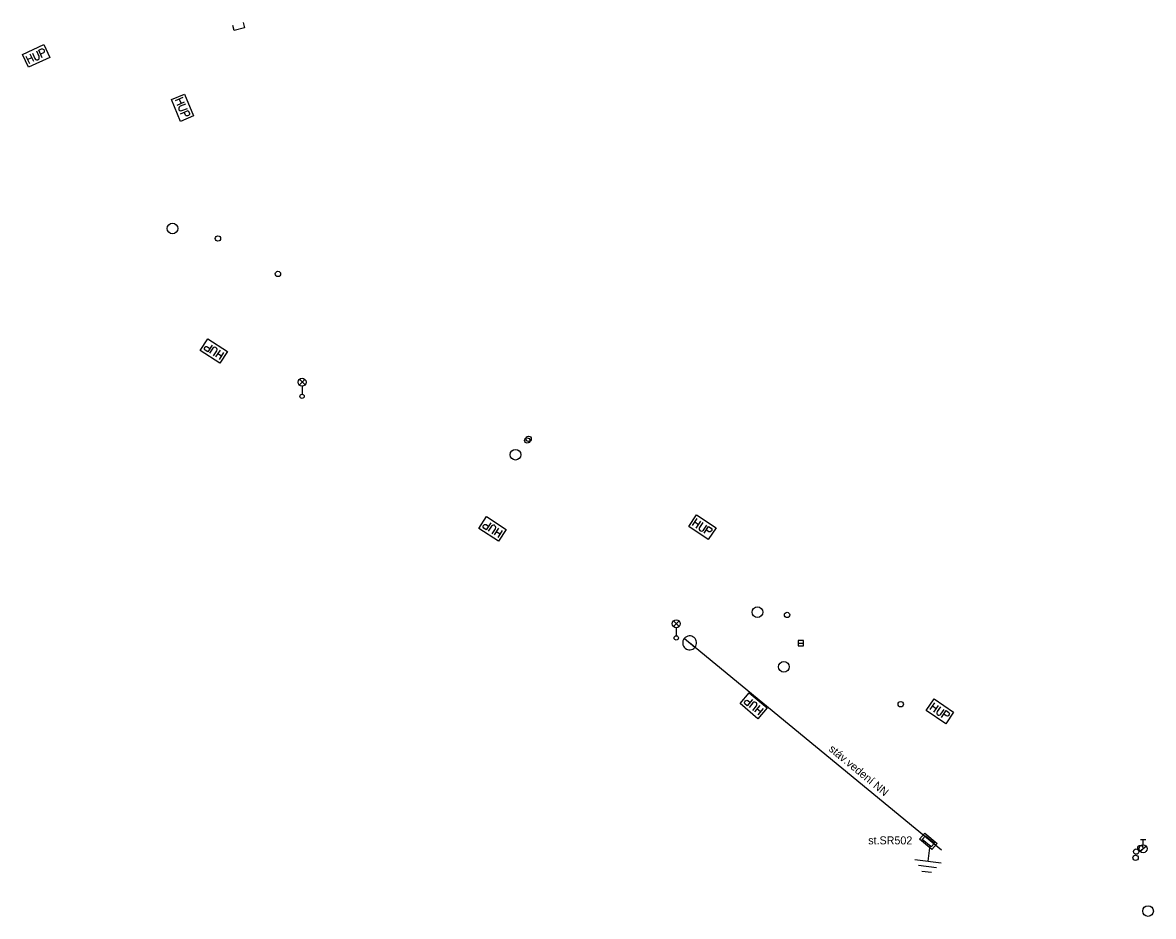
# Model space of a CAD drawing. Extents: x -762500 to -761250, y -1152983 to -1152297.
# Drawn here: x -761356.3 to -761250.4, y -1152619.7 to -1152536 of the extents above; entities that cross this region are included whole.
import ezdxf

# ---------------------------------------------------------------- set-up
doc = ezdxf.new("R2010")
doc.units = 0
for name, color, linetype in [('Vrstva 1', 7, 'Continuous'), ('Vrstva 2', 7, 'Continuous'), ('Vrstva 9', 7, 'Continuous')]:
    doc.layers.add(name, color=color, linetype=linetype)

msp = doc.modelspace()

# ---------------------------------------------------------------- linework, layer by layer
at = {"layer": 'Vrstva 1'}
for p, q in [((-761293.372, -1152594.478), (-761294.368, -1152593.642)), ((-761270.28, -1152613.45), (-761293.87, -1152594.06)), ((-761271.539, -1152614.483), (-761271.351, -1152612.995)), ((-761272.779, -1152614.327), (-761270.298, -1152614.639)), ((-761272.444, -1152614.873), (-761270.758, -1152615.085)), ((-761272.11, -1152615.419), (-761271.217, -1152615.532))]:
    msp.add_line(p, q, dxfattribs=at)
msp.add_lwpolyline([(-761335.695, -1152535.995), (-761335.561, -1152536.477), (-761336.525, -1152536.745), (-761336.659, -1152536.263)], dxfattribs=at)
for points in [[(-761271.173, -1152613.406), (-761272.326, -1152612.447), (-761271.847, -1152611.87), (-761270.693, -1152612.83)], [(-761271.231, -1152613.163), (-761272.077, -1152612.46), (-761271.789, -1152612.114), (-761270.943, -1152612.817)]]:
    msp.add_lwpolyline(points, close=True, dxfattribs=at)
for start, end in [(140.00887, 320.00887), (320.00887, 140.00887)]:
    msp.add_arc((-761293.87, -1152594.06), 0.65, start, end, dxfattribs=at)
at = {"layer": 'Vrstva 9'}
for p, q in [((-761330.434, -1152569.918), (-761329.906, -1152569.39)), ((-761329.898, -1152569.915), (-761330.426, -1152569.386)), ((-761330.17, -1152570.03), (-761330.17, -1152570.78)), ((-761295.384, -1152592.528), (-761294.856, -1152592)), ((-761294.848, -1152592.525), (-761295.376, -1152591.996)), ((-761295.12, -1152592.64), (-761295.12, -1152593.39)), ((-761283.71, -1152594.09), (-761283.21, -1152594.09)), ((-761251.64, -1152612.455), (-761251.14, -1152612.455)), ((-761251.39, -1152612.955), (-761251.39, -1152612.455)), ((-761251.684, -1152613.561), (-761251.094, -1152613.098))]:
    msp.add_line(p, q, dxfattribs=at)
for points in [[(-761356.35, -1152538.968), (-761354.35, -1152538.052), (-761353.8, -1152539.252), (-761355.8, -1152540.168), (-761356.35, -1152538.968)], [(-761355.435, -1152538.852), (-761355.205, -1152539.353), (-761355.132, -1152539.439), (-761355.04, -1152539.477), (-761354.94, -1152539.472), (-761354.883, -1152539.445), (-761354.814, -1152539.373), (-761354.787, -1152539.28), (-761354.803, -1152539.169), (-761355.033, -1152538.667)], [(-761354.835, -1152538.577), (-761354.575, -1152538.458), (-761354.476, -1152538.453), (-761354.431, -1152538.472), (-761354.373, -1152538.524), (-761354.327, -1152538.624), (-761354.325, -1152538.704), (-761354.34, -1152538.749), (-761354.409, -1152538.821), (-761354.669, -1152538.94)], [(-761354.514, -1152539.277), (-761354.835, -1152538.577)], [(-761356.035, -1152539.126), (-761355.715, -1152539.826)], [(-761355.884, -1152539.456), (-761355.482, -1152539.272)], [(-761355.313, -1152539.642), (-761355.633, -1152538.942)], [(-761341.172, -1152542.698), (-761340.329, -1152544.73), (-761341.548, -1152545.236), (-761342.392, -1152543.204), (-761341.172, -1152542.698)], [(-761341.342, -1152543.007), (-761342.053, -1152543.302)], [(-761341.884, -1152543.71), (-761341.173, -1152543.415)], [(-761341.089, -1152543.616), (-761341.599, -1152543.828), (-761341.687, -1152543.898), (-761341.728, -1152543.989), (-761341.727, -1152544.089), (-761341.703, -1152544.147), (-761341.633, -1152544.219), (-761341.541, -1152544.249), (-761341.43, -1152544.236), (-761340.92, -1152544.024)], [(-761341.677, -1152543.146), (-761341.508, -1152543.554)], [(-761341.547, -1152544.521), (-761340.836, -1152544.226)], [(-761340.836, -1152544.226), (-761340.727, -1152544.49), (-761340.725, -1152544.589), (-761340.746, -1152544.633), (-761340.801, -1152544.69), (-761340.902, -1152544.732), (-761340.982, -1152544.731), (-761341.027, -1152544.714), (-761341.096, -1152544.643), (-761341.206, -1152544.379)], [(-761337.864, -1152567.885), (-761339.718, -1152566.7), (-761339.007, -1152565.588), (-761337.153, -1152566.772), (-761337.864, -1152567.885)], [(-761339.014, -1152566.823), (-761339.255, -1152566.669), (-761339.312, -1152566.589), (-761339.321, -1152566.541), (-761339.308, -1152566.463), (-761339.249, -1152566.371), (-761339.183, -1152566.326), (-761339.137, -1152566.314), (-761339.039, -1152566.332), (-761338.798, -1152566.486)], [(-761338.599, -1152566.175), (-761339.014, -1152566.823)], [(-761338.457, -1152567.179), (-761338.16, -1152566.714), (-761338.128, -1152566.606), (-761338.146, -1152566.508), (-761338.205, -1152566.427), (-761338.258, -1152566.393), (-761338.356, -1152566.374), (-761338.448, -1152566.402), (-761338.533, -1152566.476), (-761338.83, -1152566.941)], [(-761337.859, -1152566.648), (-761338.274, -1152567.296)], [(-761337.706, -1152567.229), (-761338.078, -1152566.991)], [(-761337.901, -1152567.534), (-761337.487, -1152566.886)], [(-761311.776, -1152584.546), (-761313.621, -1152583.348), (-761312.903, -1152582.241), (-761311.057, -1152583.439), (-761311.776, -1152584.546)], [(-761293.218, -1152582.071), (-761291.391, -1152583.296), (-761292.126, -1152584.393), (-761293.954, -1152583.167), (-761293.218, -1152582.071)], [(-761312.918, -1152583.477), (-761313.158, -1152583.321), (-761313.215, -1152583.24), (-761313.223, -1152583.192), (-761313.21, -1152583.115), (-761313.15, -1152583.023), (-761313.084, -1152582.978), (-761313.037, -1152582.967), (-761312.94, -1152582.986), (-761312.7, -1152583.142)], [(-761312.499, -1152582.831), (-761312.918, -1152583.477)], [(-761312.364, -1152583.836), (-761312.064, -1152583.373), (-761312.031, -1152583.266), (-761312.048, -1152583.168), (-761312.106, -1152583.086), (-761312.159, -1152583.052), (-761312.257, -1152583.032), (-761312.35, -1152583.059), (-761312.435, -1152583.133), (-761312.735, -1152583.596)], [(-761293.189, -1152582.422), (-761293.618, -1152583.061)], [(-761293.391, -1152582.723), (-761293.024, -1152582.97)], [(-761293.251, -1152583.308), (-761292.822, -1152582.668)], [(-761292.641, -1152582.79), (-761292.948, -1152583.248), (-761292.983, -1152583.355), (-761292.967, -1152583.453), (-761292.91, -1152583.536), (-761292.858, -1152583.571), (-761292.76, -1152583.592), (-761292.667, -1152583.567), (-761292.581, -1152583.494), (-761292.274, -1152583.036)], [(-761292.521, -1152583.797), (-761292.093, -1152583.157)], [(-761292.093, -1152583.157), (-761291.855, -1152583.316), (-761291.799, -1152583.398), (-761291.792, -1152583.447), (-761291.806, -1152583.524), (-761291.867, -1152583.615), (-761291.934, -1152583.658), (-761291.981, -1152583.669), (-761292.078, -1152583.649), (-761292.315, -1152583.489)], [(-761311.762, -1152583.309), (-761312.181, -1152583.955)], [(-761311.613, -1152583.891), (-761311.984, -1152583.651)], [(-761311.811, -1152584.196), (-761311.392, -1152583.55)], [(-761287.466, -1152601.158), (-761289.151, -1152599.744), (-761288.302, -1152598.733), (-761286.618, -1152600.147), (-761287.466, -1152601.158)], [(-761288.469, -1152599.957), (-761288.688, -1152599.774), (-761288.735, -1152599.686), (-761288.737, -1152599.637), (-761288.714, -1152599.562), (-761288.643, -1152599.478), (-761288.573, -1152599.442), (-761288.525, -1152599.436), (-761288.431, -1152599.467), (-761288.212, -1152599.651)], [(-761287.974, -1152599.368), (-761288.469, -1152599.957)], [(-761287.963, -1152600.382), (-761287.608, -1152599.959), (-761287.563, -1152599.856), (-761287.568, -1152599.757), (-761287.615, -1152599.669), (-761287.664, -1152599.628), (-761287.759, -1152599.597), (-761287.854, -1152599.612), (-761287.947, -1152599.675), (-761288.302, -1152600.098)], [(-761287.301, -1152599.932), (-761287.796, -1152600.522)], [(-761287.225, -1152600.528), (-761287.563, -1152600.244)], [(-761287.458, -1152600.806), (-761286.963, -1152600.216)], [(-761270.959, -1152599.31), (-761269.138, -1152600.546), (-761269.88, -1152601.638), (-761271.7, -1152600.402), (-761270.959, -1152599.31)], [(-761270.931, -1152599.661), (-761271.364, -1152600.298)], [(-761271.135, -1152599.961), (-761270.769, -1152600.21)], [(-761270.998, -1152600.546), (-761270.565, -1152599.909)], [(-761270.385, -1152600.032), (-761270.695, -1152600.489), (-761270.73, -1152600.595), (-761270.715, -1152600.694), (-761270.659, -1152600.777), (-761270.607, -1152600.812), (-761270.509, -1152600.834), (-761270.416, -1152600.809), (-761270.329, -1152600.737), (-761270.019, -1152600.28)], [(-761270.272, -1152601.04), (-761269.839, -1152600.403)], [(-761269.839, -1152600.403), (-761269.602, -1152600.563), (-761269.547, -1152600.645), (-761269.54, -1152600.694), (-761269.555, -1152600.771), (-761269.617, -1152600.862), (-761269.683, -1152600.905), (-761269.73, -1152600.915), (-761269.827, -1152600.894), (-761270.064, -1152600.734)]]:
    msp.add_lwpolyline(points, dxfattribs=at)
msp.add_lwpolyline([(-761283.71, -1152594.341), (-761283.21, -1152594.341), (-761283.21, -1152593.84), (-761283.71, -1152593.84)], close=True, dxfattribs=at)
for centre, radius in [((-761342.31, -1152555.27), 0.5), ((-761338.05, -1152556.2), 0.25), ((-761332.43, -1152559.52), 0.25), ((-761330.17, -1152569.655), 0.375), ((-761330.17, -1152570.98), 0.2), ((-761308.95, -1152574.96), 0.25), ((-761309.08, -1152575.11), 0.25), ((-761310.18, -1152576.44), 0.5), ((-761287.52, -1152591.18), 0.5), ((-761284.74, -1152591.44), 0.25), ((-761295.12, -1152592.265), 0.375), ((-761295.12, -1152593.59), 0.2), ((-761285.04, -1152596.3), 0.5), ((-761274.1, -1152599.8), 0.25), ((-761251.39, -1152613.33), 0.375), ((-761252.1, -1152614.18), 0.25), ((-761252.04, -1152613.6), 0.25), ((-761251.65, -1152613.27), 0.25), ((-761250.93, -1152619.16), 0.5)]:
    msp.add_circle(centre, radius, dxfattribs=at)

# ---------------------------------------------------------------- texts
at = {"layer": 'Vrstva 2'}
msp.add_text('stáv.vedení NN', height=0.75, rotation=320.555, dxfattribs=at).set_placement((-761280.91, -1152604.1))
msp.add_text('st.SR502', height=0.75, dxfattribs=at).set_placement((-761277.14, -1152612.92))

doc.saveas('drawing.dxf')
